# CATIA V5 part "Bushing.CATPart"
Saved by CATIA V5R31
Part number: Bushing
Bounding box of the stored display mesh (mm): x -13.45 to 13.45, y 0 to 63, z -13.45 to 13.45
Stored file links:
  D:\PROJECTS\Project 2021\US EDITION\CATIA V5 6R 2021\Resources\Part Files\c12_catia_v5_6r2021_prt\c12_catia_v5-6r2021 figr_12-49\Bushing.CATPart
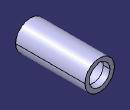
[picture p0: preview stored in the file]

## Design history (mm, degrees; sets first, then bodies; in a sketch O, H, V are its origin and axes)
Body1 (main body)
  Sketch1 on zx-plane, origin (0, 0, 0), H (-1, 0, 0), V (0, 0, 1)
    circle A1 centre (0, 0) radius 9.5
    circle A2 centre (0, 0) radius 13.45
    radius A1 = 9.5
    radius A2 = 13.45
  Pad1: profile Sketch1, direction (0, 1, 0), length 63
  Sketch2 on face of Pad1, origin (0, 63, 0), H (-1, 0, 0), V (0, 0, 1)
    line L1 (-1.5, 9.3808) -> (1.5, 9.3808)
    line L2 (1.5, 9.3808) -> (1.5, 10.1808)
    line L3 (1.5, 10.1808) -> (-1.5, 10.1808)
    line L4 (-1.5, 10.1808) -> (-1.5, 9.3808)
    point P2 (1.5, 9.3808)
    reference projected circle E1 centre (0, 0) radius 9.5 from edge of Pad1
    length L3 = 3
    length L2 = 0.8
    distance V L4 = 1.5
    horizontal: L1 H, L3 H
    vertical: L2 V, L4 V
    coincidence: P2 E1
  Pocket1: profile Sketch2, direction (0, -1, 0), through (limit type 6)
  Sketch3 on xy-plane, origin (0, 0, 0), H (1, 0, 0), V (0, 1, 0)
    line L1 (9.5, 57) -> (10.3, 57)
    line L2 (10.3, 57) -> (10.3, 49)
    line L3 (10.3, 49) -> (9.5, 49)
    line L4 (9.5, 49) -> (9.5, 57)
    reference projected line E1 (13.45, 63) -> (-13.45, 63) from edge of Pad1
    length L2 = 8
    length L1 = 0.8
    distance L3 E1 = 14
    distance V L4 = 9.5
    horizontal: L1 H, L3 H
    vertical: L2 V, L4 V
  Groove1: profile Sketch3, axis axis of face of Pad1, angle 360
